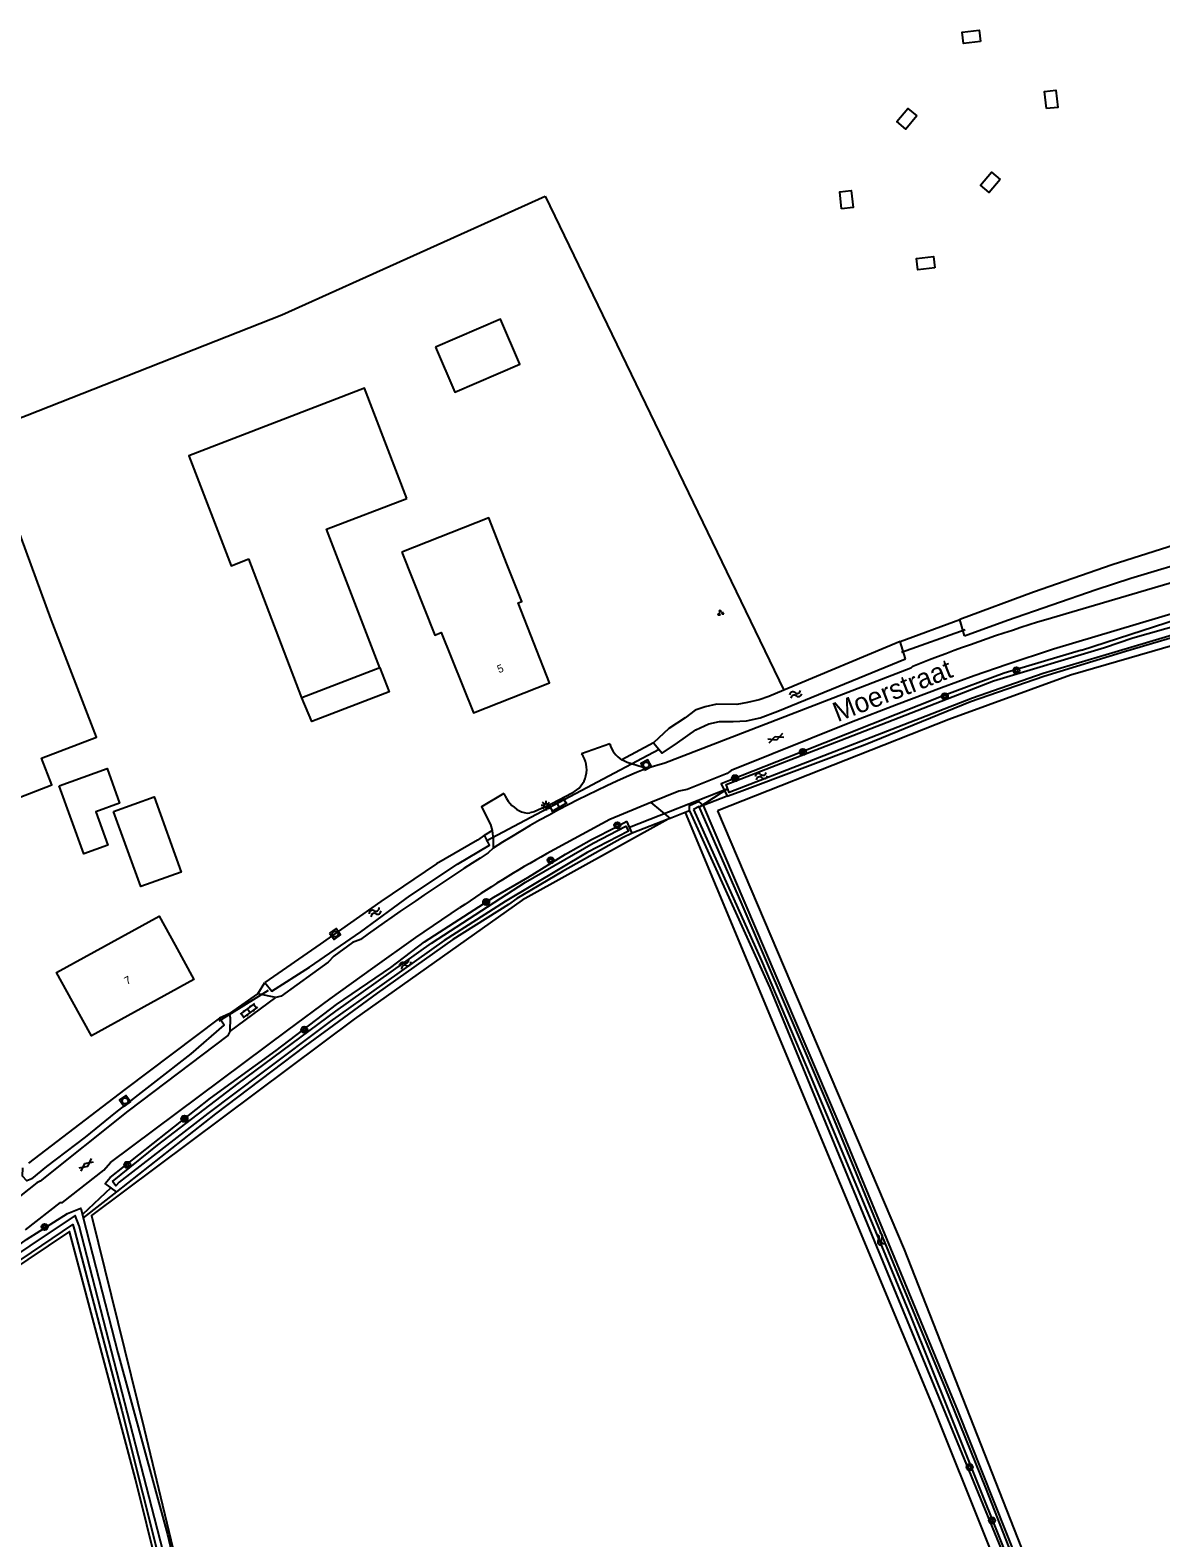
# Model space of a CAD drawing. Extents: x 133000 to 136000, y 400500 to 403500.
# Drawn here: x 134850.9 to 134995, y 400607.1 to 400799.3 of the extents above; entities that cross this region are included whole.
import ezdxf

# ---------------------------------------------------------------- set-up
doc = ezdxf.new("R2010")
doc.units = 0
for name, color, linetype in [('gg-afsc-draadraster', 7, 'Continuous'), ('gg-anno-huisnummerreeks BGT', 7, 'Continuous'), ('gg-anno-openbare ruimte label', 7, 'Continuous'), ('gg-bbg-bijgebouw', 7, 'Continuous'), ('gg-bbg-bijgebouw onder overbouw', 7, 'Continuous'), ('gg-bbg-gedigitaliseerde bijgebouw', 7, 'Continuous'), ('gg-bbg-hoofdgebouw', 7, 'Continuous'), ('gg-bbg-hoogspanningsmast', 7, 'Continuous'), ('gg-bbg-pand overbouw', 7, 'Continuous'), ('gg-knt-bronhoudergrens', 7, 'Continuous'), ('gg-knt-verharding', 7, 'Continuous'), ('gg-kntw-bovenkant insteek waterloop', 7, 'Continuous'), ('gg-kntw-greppel-droge sloot', 7, 'Continuous'), ('gg-kntw-waterlijn', 7, 'Continuous'), ('gg-kwrk-duiker nz buis', 7, 'Continuous'), ('gt-grn-groengrens', 7, 'Continuous'), ('gt-symb-boom', 7, 'Continuous'), ('gt-symb-gesloten verharding', 7, 'Continuous'), ('gt-symb-groenvak', 7, 'Continuous'), ('gt-symb-klinker verharding', 7, 'Continuous'), ('gt-symb-lichtmast', 7, 'Continuous'), ('gt-symb-rioolschacht', 7, 'Continuous'), ('gt-symb-watersymbool', 7, 'Continuous')]:
    doc.layers.add(name, color=color, linetype=linetype)

# ---------------------------------------------------------------- blocks, each defined once
blk = doc.blocks.new('gt0-BOOM')
at = {"layer": 'gt-symb-boom'}
for radius in [0.4, 0.2]:
    blk.add_circle((0, 0), radius, dxfattribs=at)
blk = doc.blocks.new('gt0-WA')
at = {"layer": 'gt-symb-watersymbool'}
for centre, start, end in [((-0.32, 0.02), 28.0725, 151.9275), ((0.43, 0.42), 208.0725, 331.9275), ((-0.32, -0.43), 28.0725, 151.9275), ((0.43, -0.03), 208.0725, 331.9275)]:
    blk.add_arc(centre, 0.425, start, end, dxfattribs=at)
blk = doc.blocks.new('gt0-GESVH1')
at = {"layer": 'gt-symb-gesloten verharding'}
for p, q in [((-0.99, -0.26), (0.01, 0.24)), ((0.01, -0.26), (-0.99, 0.24)), ((0.01, 0.24), (1.01, -0.26)), ((1.01, 0.24), (0.01, -0.26))]:
    blk.add_line(p, q, dxfattribs=at)
blk = doc.blocks.new('gt0-RS')
at = {"layer": 'gt-symb-rioolschacht'}
blk.add_lwpolyline([(-0.5, -0.5), (0.5, -0.5), (0.5, 0.5), (-0.5, 0.5)], close=True, dxfattribs=at)
blk.add_circle((0, 0), 0.375, dxfattribs=at)
blk = doc.blocks.new('gt0-LMAST')
at = {"layer": 'gt-symb-lichtmast'}
for p, q in [((-0.18, 0.17), (-0.45, 0.44)), ((-0.01, 0.25), (-0.01, 0.62)), ((0.17, 0.17), (0.44, 0.44)), ((-0.26, 0), (-0.63, 0)), ((-0.18, -0.18), (-0.45, -0.45)), ((-0.01, -0.25), (-0.01, -0.63)), ((0.44, -0.45), (0.17, -0.18)), ((0.24, 0), (0.62, 0))]:
    blk.add_line(p, q, dxfattribs=at)
blk.add_circle((-0.01, 0), 0.25, dxfattribs=at)
blk = doc.blocks.new('gt0-KL1')
at = {"layer": 'gt-symb-klinker verharding'}
for p, q in [((-1.15, 0.3), (1.15, 0.3)), ((-1, -0.3), (-1, 0.3)), ((-0.5, 0.3), (-0.5, 0.45)), ((0, -0.3), (0, 0.3)), ((0.5, 0.3), (0.5, 0.45)), ((1, -0.3), (1, 0.3)), ((-1.15, -0.3), (1.15, -0.3)), ((-0.5, -0.45), (-0.5, -0.3)), ((0.5, -0.45), (0.5, -0.3))]:
    blk.add_line(p, q, dxfattribs=at)
blk = doc.blocks.new('gt0-GRVAK')
at = {"layer": 'gt-symb-groenvak'}
for p, q in [((-0.11, 0.19), (-0.23, 0.24)), ((-0.18, 0.15), (0.09, 0.15)), ((-0.09, 0.21), (-0.16, 0.32)), ((-0.05, 0.21), (-0.05, 0.39)), ((0, 0.21), (0.06, 0.32)), ((0.01, 0.19), (0.13, 0.24)), ((0.26, -0.05), (0.2, 0.06)), ((0.3, -0.05), (0.3, 0.13)), ((0.35, -0.05), (0.41, 0.06)), ((-0.25, -0.23), (-0.36, -0.18)), ((-0.32, -0.26), (-0.05, -0.26)), ((-0.23, -0.21), (-0.29, -0.1)), ((-0.18, -0.2), (-0.18, -0.02)), ((-0.14, -0.21), (-0.07, -0.1)), ((-0.12, -0.23), (0, -0.18)), ((0.24, -0.07), (0.12, -0.02)), ((0.17, -0.11), (0.44, -0.11)), ((0.37, -0.07), (0.49, -0.02))]:
    blk.add_line(p, q, dxfattribs=at)

msp = doc.modelspace()

# ---------------------------------------------------------------- linework, layer by layer
at = {"layer": 'gg-afsc-draadraster'}
msp.add_line((134916.57, 400778.18), (134946.99, 400715.19), dxfattribs=at)
for points in [[(134827.39, 400727), (134823.76, 400736.57), (134824.56, 400736.88), (134827.42, 400736.42), (134841.93, 400698.59), (134853.72, 400703.11), (134852.41, 400706.51), (134859.38, 400709.18), (134853.63, 400724.18), (134847.88, 400739.87), (134846.75, 400748.81), (134850.58, 400750.24), (134883, 400763.02), (134916.57, 400778.18)], [(135015.55, 400686.93), (135008, 400703.4), (134999.78, 400721.8), (134983.52, 400717.09), (134968, 400711.46), (134941.76, 400701.07)], [(134938.53, 400699.8), (134962.32, 400643.88), (134982.78, 400591.74), (134984.96, 400591.02), (134994.75, 400591.28), (135005.59, 400592.61), (135017.83, 400595.97)]]:
    msp.add_lwpolyline(points, dxfattribs=at)
at = {"layer": 'gg-bbg-bijgebouw'}
msp.add_line((134885.58, 400714.22), (134878.82, 400731.92), dxfattribs=at)
for points in [[(134898.95, 400739.64), (134893.55, 400753.67), (134871.15, 400745.05), (134876.54, 400731.04), (134878.82, 400731.92)], [(134895.52, 400718.04), (134888.72, 400735.71), (134898.95, 400739.64)]]:
    msp.add_lwpolyline(points, dxfattribs=at)
at = {"layer": 'gg-bbg-bijgebouw onder overbouw'}
msp.add_line((134895.52, 400718.04), (134885.58, 400714.22), dxfattribs=at)
at = {"layer": 'gg-bbg-gedigitaliseerde bijgebouw'}
for points in [[(134902.61, 400758.93), (134905.08, 400753.19), (134913.33, 400756.74), (134910.87, 400762.48), (134902.61, 400758.93)], [(134854.65, 400702.99), (134860.74, 400705.2), (134862.34, 400700.79), (134859.31, 400699.69), (134860.86, 400695.42), (134857.8, 400694.31), (134854.65, 400702.99)], [(134861.58, 400699.71), (134866.73, 400701.58), (134870.2, 400692.01), (134865.05, 400690.15), (134861.58, 400699.71)]]:
    msp.add_lwpolyline(points, dxfattribs=at)
at = {"layer": 'gg-bbg-hoofdgebouw'}
for points in [[(134898.29, 400732.76), (134902.5, 400722.2), (134903.32, 400722.53), (134907.42, 400712.29), (134917.14, 400716.13), (134913.11, 400726.33), (134913.58, 400726.51), (134911.74, 400731.16), (134909.38, 400737.14), (134898.29, 400732.76)], [(134856.35, 400675.49), (134854.32, 400679.18), (134867.38, 400686.36), (134869.41, 400682.67), (134871.82, 400678.29), (134858.76, 400671.11), (134856.35, 400675.49)]]:
    msp.add_lwpolyline(points, dxfattribs=at)
at = {"layer": 'gg-bbg-hoogspanningsmast'}
for points in [[(134972.05, 400797.86), (134969.88, 400797.62), (134969.71, 400799.08), (134971.89, 400799.32), (134972.05, 400797.86)], [(134980.44, 400789.32), (134980.2, 400791.49), (134981.65, 400791.66), (134981.9, 400789.48), (134980.44, 400789.32)], [(134963.91, 400788.4), (134962.51, 400786.72), (134961.38, 400787.66), (134962.78, 400789.34), (134963.91, 400788.4)], [(134974.56, 400780.3), (134973.16, 400778.62), (134972.03, 400779.56), (134973.43, 400781.24), (134974.56, 400780.3)], [(134954.35, 400776.53), (134954.1, 400778.71), (134955.56, 400778.87), (134955.81, 400776.7), (134954.35, 400776.53)], [(134966.21, 400769.01), (134964.04, 400768.77), (134963.87, 400770.22), (134966.05, 400770.47), (134966.21, 400769.01)]]:
    msp.add_lwpolyline(points, dxfattribs=at)
at = {"layer": 'gg-bbg-pand overbouw'}
msp.add_lwpolyline([(134895.52, 400718.04), (134896.7, 400714.99), (134886.82, 400711.19), (134885.58, 400714.22)], dxfattribs=at)
at = {"layer": 'gg-knt-bronhoudergrens'}
for p, q in [((134961.81, 400721.39), (134969.39, 400724.21)), ((134941.76, 400701.07), (134938.53, 400699.8))]:
    msp.add_line(p, q, dxfattribs=at)
for points in [[(134932.23, 400698.74), (134913.64, 400688.44), (134892.23, 400673.25), (134858.78, 400648.21), (134865.48, 400621.03), (134873.57, 400587.23)], [(134934.39, 400699.58), (134966.02, 400623.8), (134979.6, 400589.85)]]:
    msp.add_lwpolyline(points, dxfattribs=at)
at = {"layer": 'gg-knt-verharding'}
for p, q in [((134980.38, 400724.18), (135000, 400730.01)), ((134924.8, 400708.35), (134921.21, 400707.07)), ((134909.95, 400695.06), (134909.32, 400694.45)), ((134876.39, 400671.67), (134882.25, 400676.02)), ((134876.4, 400673.97), (134879.94, 400676.46)), ((134882.25, 400676.02), (134879.94, 400676.46)), ((134876.45, 400673.52), (134876.4, 400673.97)), ((134876.45, 400673.52), (134876.39, 400671.67))]:
    msp.add_line(p, q, dxfattribs=at)
for points in [[(135000, 400726), (134981.33, 400720.41), (134975.43, 400718.46), (134971.23, 400717.01), (134967.06, 400715.5), (134961.33, 400713.32), (134955.62, 400711.09), (134940.28, 400704.97), (134939.77, 400704.55), (134934.67, 400702.52), (134933.62, 400702.32), (134930.04, 400700.85)], [(134963.43, 400718.23), (134963.18, 400717.99), (134931.83, 400705.89), (134929.48, 400705.22)], [(134929.48, 400705.22), (134927.01, 400705.95), (134926.34, 400706.29)], [(134911.31, 400702.03), (134908.47, 400700.33), (134909.62, 400698.08), (134909.81, 400697.29)], [(134920, 400702.08), (134917.41, 400700.71), (134915.19, 400699.7), (134914.62, 400699.55)], [(134930.04, 400700.85), (134924.81, 400698.69), (134916.74, 400694.32)], [(134909.81, 400697.29), (134909.95, 400696.18), (134909.95, 400695.06)], [(134850.37, 400646.39), (134854.82, 400649.88), (134855.08, 400649.88), (134860.33, 400654), (134861.17, 400654.96), (134883.76, 400671.86), (134889.16, 400675.84), (134894.61, 400679.76), (134900.1, 400683.64), (134905.66, 400687.43)], [(134893.03, 400683.42), (134892.04, 400683.01), (134889.64, 400681.3), (134888.91, 400680.5), (134882.95, 400676.17), (134882.25, 400676.02)], [(134876.39, 400671.67), (134876.13, 400671.16), (134863.4, 400661.54), (134852.23, 400652.58), (134851.8, 400652.4), (134848.75, 400649.98), (134848.12, 400649.3), (134843.34, 400645.65), (134837.23, 400641.17), (134832.58, 400637.9), (134827.88, 400634.68), (134824.55, 400632.48), (134821.18, 400630.34), (134820, 400630.01)]]:
    msp.add_lwpolyline(points, dxfattribs=at)
for centre, radius, start, end in [((135049.27, 400500.7), 233.85, 107.1326, 111.5348), ((134928.31, 400709.37), 3.66, 196.079, 237.4032), ((134918.53, 400705.08), 3.34, 296.0083, 36.5312), ((134977.62, 400588.91), 125.88, 112.4819, 122.5152), ((134915.51, 400703.75), 4.54, 202.3517, 239.6522), ((134914.33, 400701.66), 2.13, 238.5293, 277.9925), ((135108.13, 400383.34), 369.21, 122.5794, 125.6327), ((134980.75, 400579.02), 131.87, 119.0369, 124.7086)]:
    msp.add_arc(centre, radius, start, end, dxfattribs=at)
at = {"layer": 'gg-kntw-bovenkant insteek waterloop'}
for p, q in [((134969.99, 400722.12), (134969.39, 400724.21)), ((134961.81, 400721.39), (134946.99, 400715.19)), ((134962.47, 400719.17), (134961.81, 400721.39)), ((134939.78, 400701.68), (134941.29, 400702.24)), ((134927.66, 400696.96), (134926.98, 400698.49))]:
    msp.add_line(p, q, dxfattribs=at)
for points in [[(135000, 400734.66), (134998.61, 400734.27), (134988.82, 400731.15), (134978.8, 400727.69), (134969.39, 400724.21)], [(134969.99, 400722.12), (134975.5, 400724.12), (134986.79, 400728.03), (134991.2, 400729.45), (135000, 400732.1)], [(134984.92, 400720.28), (135008.1, 400727.81), (135010.06, 400727.68), (135010.65, 400726.26)], [(134941.29, 400702.24), (134957.33, 400708.25), (134970.78, 400713.73), (134980.13, 400716.96), (134990.53, 400720.16), (135000, 400722.95)], [(134984.92, 400720.28), (134975.08, 400717.37), (134967.3, 400714.47), (134949.12, 400707.23), (134940.05, 400703.68), (134939, 400703.24), (134939.78, 400701.68)], [(134930.37, 400708.48), (134931.47, 400707.14), (134933.43, 400708.46), (134935.75, 400710.12), (134937.44, 400710.91), (134938.8, 400711.2), (134940.51, 400711.18), (134942.21, 400711.27), (134943.98, 400711.65), (134946.22, 400712.51), (134962.47, 400719.17)], [(134946.99, 400715.19), (134945.08, 400714.39), (134943.82, 400713.96), (134942.36, 400713.62), (134940.99, 400713.37), (134938.44, 400713.42), (134936.97, 400713.08), (134935.7, 400712.63), (134934.41, 400711.68), (134932.35, 400710.31), (134930.37, 400708.48)], [(134934.95, 400699.8), (134934.95, 400700.47), (134936.12, 400700.98), (134936.7, 400700.48)], [(134936.7, 400700.48), (134953.87, 400660.27), (134969.1, 400623.35), (134981.5, 400592.2), (134981.86, 400590.5), (134981.8, 400589.67)], [(134934.95, 400699.8), (134945.21, 400677.23), (134966.39, 400625.82), (134975.6, 400603.46), (134980.29, 400589.79)], [(134861.93, 400651.23), (134860.52, 400652.29), (134861.15, 400653.07), (134873.93, 400663.18), (134882.3, 400669.26), (134890, 400675.12), (134896.9, 400679.85), (134901.19, 400683.09), (134910.04, 400688.8), (134914.35, 400691.33), (134919.18, 400694.3), (134922.46, 400696.17), (134925.64, 400697.75), (134926.98, 400698.49)], [(134927.66, 400696.96), (134926.43, 400696.36), (134918.79, 400692.06), (134912.94, 400688.63), (134911.91, 400687.87), (134904.81, 400683.39), (134895.17, 400676.56), (134885.93, 400669.82), (134874.56, 400661.2), (134861.93, 400651.23)], [(134880.84, 400677.94), (134881.75, 400676.8), (134886.53, 400679.87), (134893.08, 400684.37), (134899.32, 400688.98), (134905.4, 400692.99), (134909.46, 400695.44), (134908.86, 400696.72)], [(134908.86, 400696.72), (134907.93, 400696.05), (134902.74, 400693.05), (134895.64, 400688.27), (134887.9, 400682.82), (134880.84, 400677.94)], [(134812.36, 400617.12), (134811.09, 400619.34), (134812.99, 400620.47), (134817.75, 400622.98), (134821.6, 400625.24), (134824.99, 400627.45), (134828.82, 400630.26), (134835.82, 400634.99), (134843.34, 400639.95), (134850.46, 400645.18), (134855.71, 400648.48), (134857.4, 400649.16), (134857.72, 400647.91)], [(134857.72, 400647.91), (134862.11, 400630.73), (134868.45, 400607.57), (134872.39, 400590.72), (134872.61, 400588.76), (134872.57, 400588.23)], [(134869.98, 400588.16), (134870.07, 400591.67), (134864.37, 400614.6), (134855.95, 400646.17), (134842.58, 400637.22), (134828.61, 400627.71), (134812.36, 400617.12)]]:
    msp.add_lwpolyline(points, dxfattribs=at)
at = {"layer": 'gg-kntw-greppel-droge sloot'}
for points in [[(134875.09, 400673.37), (134863, 400664.28), (134850.75, 400654.89)], [(134851.14, 400652.89), (134853.09, 400654.45), (134858, 400658.21), (134861.88, 400661.36), (134871.46, 400668.85), (134875.66, 400672.49), (134875.09, 400673.37)], [(134851.14, 400652.89), (134850.53, 400652.66), (134849.97, 400653.24), (134850, 400654.31)]]:
    msp.add_lwpolyline(points, dxfattribs=at)
at = {"layer": 'gg-kntw-waterlijn'}
for points in [[(135009.09, 400727.26), (135009.61, 400726.67), (135009.49, 400726.19), (135002.03, 400723.87), (134989.19, 400720.04), (134980.04, 400717.31), (134971.03, 400714.18), (134961.5, 400710.48), (134940.03, 400702.15), (134939.64, 400703.15), (134954.25, 400708.82), (134973.69, 400716.37), (134987.83, 400720.64), (134991.46, 400721.86), (135003.76, 400725.35), (135009.09, 400727.26)], [(134935.49, 400699.97), (134944.14, 400680.68), (134950.36, 400666.07), (134959.62, 400643.84), (134963.16, 400635.32), (134967.99, 400623.26), (134978.01, 400598.29), (134980.28, 400591.8), (134980.63, 400590.22), (134981.42, 400590.39), (134981.02, 400592.21), (134978.28, 400599.26), (134972.73, 400613.5), (134967.53, 400626.28), (134961.77, 400640.2), (134952.93, 400661.6), (134947.35, 400674.63), (134941.56, 400688.16), (134936.27, 400700.14), (134936.18, 400700.34), (134935.49, 400699.97)], [(134861.43, 400652.55), (134867.18, 400657.18), (134877.46, 400665.04), (134889.9, 400674.26), (134902.1, 400682.93), (134914.06, 400690.73), (134922.68, 400695.68), (134926.86, 400697.84), (134927.19, 400697.2), (134921.93, 400694.49), (134911.48, 400688.26), (134903.71, 400683.26), (134894.46, 400676.7), (134889.18, 400672.94), (134880.47, 400666.41), (134873.57, 400661.22), (134862.3, 400652.49), (134861.86, 400651.99), (134861.43, 400652.55)], [(134871.87, 400588.21), (134871.39, 400591.86), (134866.79, 400609.7), (134857.21, 400646.89), (134856.69, 400648.24), (134839.43, 400636.73), (134825.58, 400627.13), (134819.98, 400623.57), (134812.22, 400619.01), (134812.68, 400618.28), (134823.19, 400624.84), (134830.85, 400629.95), (134851.13, 400643.49), (134856.38, 400647.08), (134856.62, 400646.17), (134862.62, 400623.36), (134870.53, 400591.87), (134870.78, 400589.38), (134870.67, 400588.18)]]:
    msp.add_lwpolyline(points, dxfattribs=at)
at = {"layer": 'gg-kwrk-duiker nz buis'}
for p, q in [((134961.97, 400720.04), (134970.11, 400722.94)), ((134909.04, 400695.99), (134931.11, 400707.66)), ((134927.32, 400697.72), (134939.84, 400702.65)), ((134936.18, 400700.26), (134939.84, 400702.65)), ((134875.05, 400673.03), (134881.31, 400676.94)), ((134861.22, 400651.76), (134857.61, 400648.34))]:
    msp.add_line(p, q, dxfattribs=at)
at = {"layer": 'gt-grn-groengrens'}
for p, q in [((134930.37, 400708.48), (134926.34, 400706.29)), ((134930.04, 400700.85), (134932.48, 400698.84)), ((134939.78, 400701.68), (134936.7, 400700.48)), ((134932.23, 400698.74), (134927.66, 400696.96)), ((134932.48, 400698.84), (134932.23, 400698.74)), ((134934.39, 400699.58), (134932.48, 400698.84)), ((134934.95, 400699.8), (134934.39, 400699.58)), ((134908.86, 400696.72), (134909.81, 400697.29)), ((134879.94, 400676.46), (134880.84, 400677.94)), ((134876.4, 400673.97), (134875.09, 400673.37)), ((134861.93, 400651.23), (134857.72, 400647.91))]:
    msp.add_line(p, q, dxfattribs=at)

# ---------------------------------------------------------------- block references
at = {"layer": 'gt-symb-boom'}
for p in [(134976.61, 400717.7), (134967.5, 400714.41), (134949.41, 400707.3), (134940.75, 400703.97), (134925.77, 400697.97), (134917.28, 400693.51), (134909.05, 400688.19), (134885.88, 400671.9), (134870.61, 400660.55), (134863.32, 400654.68), (134852.79, 400646.77), (134970.67, 400616.14), (134973.5, 400609.35)]:
    msp.add_blockref('gt0-BOOM', p, dxfattribs=at)
at = {"layer": 'gt-symb-gesloten verharding'}
for p, rotation in [((134945.97, 400709.06), -158.41134772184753), ((134858.07, 400654.67), 37.568592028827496)]:
    msp.add_blockref('gt0-GESVH1', p, dxfattribs=dict(at, rotation=rotation))
at = {"layer": 'gt-symb-groenvak'}
msp.add_blockref('gt0-GRVAK', (134938.91, 400725.05), dxfattribs=at)
at = {"layer": 'gt-symb-klinker verharding'}
for p, rotation in [((134918.22, 400700.51), -149.99927221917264), ((134878.8, 400674.33), -143.4165788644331)]:
    msp.add_blockref('gt0-KL1', p, dxfattribs=dict(at, rotation=rotation))
at = {"layer": 'gt-symb-lichtmast'}
msp.add_blockref('gt0-LMAST', (134916.69, 400700.48), dxfattribs=at)
at = {"layer": 'gt-symb-rioolschacht'}
for p, rotation in [((134929.44, 400705.65), 28.948861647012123), ((134889.81, 400684.1), -53.90943276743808), ((134863.04, 400662.83), 35.35794257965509)]:
    msp.add_blockref('gt0-RS', p, dxfattribs=dict(at, rotation=rotation))
at = {"layer": 'gt-symb-watersymbool'}
for p, rotation in [((134948.43, 400714.65), 22.280371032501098), ((134944.05, 400704.22), 19.32248237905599), ((134894.85, 400686.86), 31.209490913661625), ((134898.69, 400680.23), 37.97050166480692), ((134959.27, 400645.19), 112.38636556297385)]:
    msp.add_blockref('gt0-WA', p, dxfattribs=dict(at, rotation=rotation))

# ---------------------------------------------------------------- texts
at = {"layer": 'gg-anno-huisnummerreeks BGT'}
for s, rotation, p in [('5', 21.6, (134910.69, 400717.34)), ('7', 28.8, (134863.28, 400677.59))]:
    msp.add_text(s, height=1, rotation=rotation, dxfattribs=at).set_placement(p)
at = {"layer": 'gg-anno-openbare ruimte label'}
msp.add_text('Moerstraat', height=2.5, rotation=21.4, dxfattribs=at).set_placement((134953.83, 400711.1))

doc.saveas('drawing.dxf')
